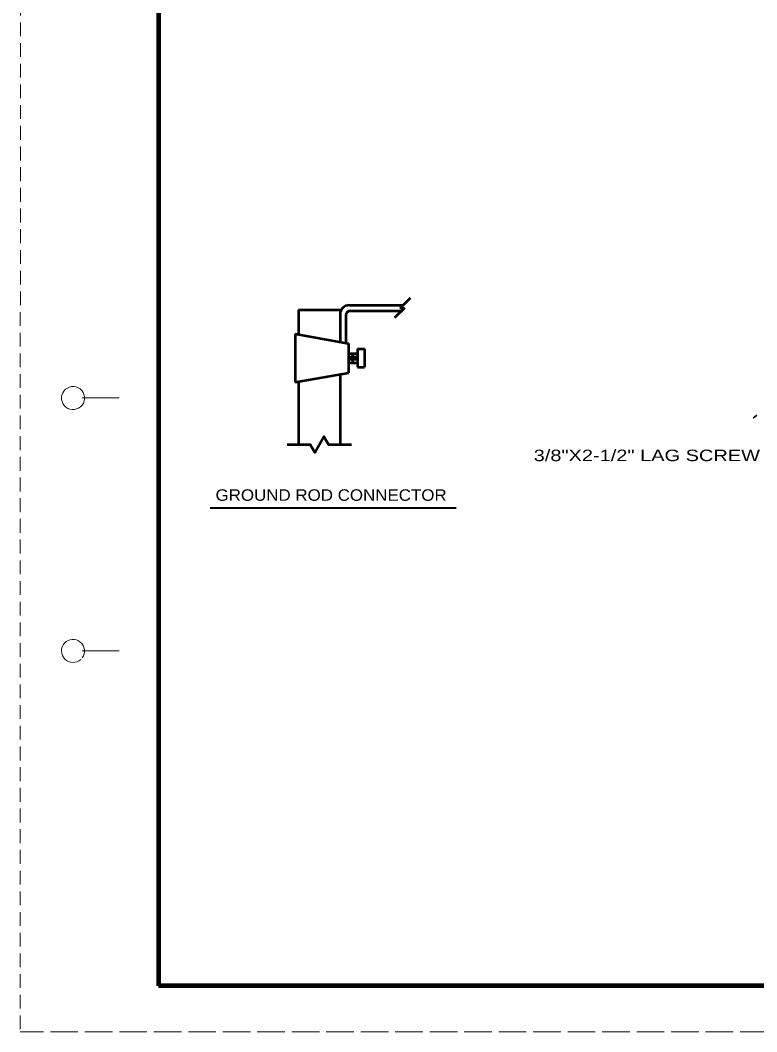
# Model space of a CAD drawing. Extents: x 12366 to 13046, y 9129 to 9570.
# Drawn here: x 12365.9 to 12526.1, y 9129.5 to 9349.5 of the extents above; entities that cross this region are included whole.
import ezdxf

# ---------------------------------------------------------------- set-up
doc = ezdxf.new("R2010")
doc.units = 0
doc.linetypes.add('LONG_DASHED', pattern=[7.5, 6, -1.5])
doc.linetypes.add('MEDIUM_DASHED', pattern=[4.5, 3, -1.5])
doc.layers.add('1', color=7, linetype='Continuous', lineweight=53)
doc.layers.add('61', color=7, linetype='Continuous', lineweight=35)

msp = doc.modelspace()

# ---------------------------------------------------------------- linework, layer by layer
at = {"layer": '1', "linetype": 'MEDIUM_DASHED', "lineweight": 13}
msp.add_line((12365.992, 9569.533), (12365.932, 9129.493), dxfattribs=at)
at = {"layer": '1'}
for p, q in [((12437.476, 9287.528), (12449.209, 9287.528)), ((12426.476, 9286.52), (12426.476, 9281.138)), ((12426.476, 9286.52), (12435.74, 9286.52)), ((12435.476, 9285.528), (12435.476, 9279.551)), ((12436.726, 9285.278), (12436.726, 9279.33)), ((12437.726, 9286.278), (12448.846, 9286.278)), ((12449.474, 9286.905), (12447.352, 9284.784)), ((12425.726, 9281.27), (12425.726, 9270.779)), ((12425.726, 9281.27), (12437.298, 9279.23)), ((12437.298, 9279.23), (12437.298, 9272.82)), ((12437.298, 9277.02), (12439.298, 9277.02)), ((12437.798, 9275.52), (12437.798, 9276.52)), ((12438.298, 9275.02), (12438.298, 9277.02)), ((12438.798, 9275.52), (12438.798, 9276.52)), ((12439.298, 9278.02), (12439.298, 9274.02)), ((12439.298, 9278.02), (12440.798, 9278.02)), ((12440.798, 9278.02), (12440.798, 9274.02)), ((12437.298, 9275.02), (12439.298, 9275.02)), ((12439.298, 9274.02), (12440.798, 9274.02)), ((12425.726, 9270.779), (12437.298, 9272.82)), ((12435.476, 9272.498), (12435.476, 9257.27)), ((12426.476, 9270.912), (12426.476, 9257.27))]:
    msp.add_line(p, q, dxfattribs=at)
at = {"layer": '1', "lineweight": 35}
msp.add_line((12525.317, 9262.922), (12526.085, 9263.578), dxfattribs=at)
at = {"layer": '1', "lineweight": 40}
msp.add_line((12407.255, 9243.427), (12460.728, 9243.427), dxfattribs=at)
at = {"layer": '1'}
for points in [[(12450.731, 9289.049), (12448.61, 9286.928), (12449.474, 9286.905)], [(12423.971, 9257.229), (12428.971, 9257.229), (12429.971, 9255.497), (12431.971, 9258.961), (12432.971, 9257.229), (12437.971, 9257.229)]]:
    msp.add_lwpolyline(points, dxfattribs=at)
for centre, radius, start in [((12437.476, 9285.528), 2, 90), ((12437.726, 9285.278), 1, 89.99931)]:
    msp.add_arc(centre, radius, start, 180, dxfattribs=at)
at = {"layer": '61', "lineweight": 13}
for p, q in [((12379.412, 9267.353), (12387.412, 9267.353)), ((12379.432, 9212.333), (12387.412, 9212.333))]:
    msp.add_line(p, q, dxfattribs=at)
at = {"layer": '61', "lineweight": 158}
msp.add_line((13035.052, 9139.493), (12395.992, 9139.513), dxfattribs=at)
at = {"layer": '61', "linetype": 'LONG_DASHED', "lineweight": 13}
msp.add_line((13045.992, 9129.513), (12365.932, 9129.493), dxfattribs=at)
at = {"layer": '61', "lineweight": 158}
msp.add_lwpolyline([(13035.032, 9559.533), (12395.992, 9559.533), (12395.992, 9139.513)], dxfattribs=at)
at = {"layer": '61', "lineweight": 13}
for centre, start, end in [((12377.409, 9267.334), 322.67175, 321.71615), ((12377.409, 9212.334), 323.13009, 312.31439)]:
    msp.add_arc(centre, 2.5, start, end, dxfattribs=at)

# ---------------------------------------------------------------- texts
at = {"layer": '1'}
for s, width, p in [('3/8"X2-1/2" LAG SCREW', 1.3, (12477.593, 9253.608)), ('GROUND ROD CONNECTOR', 1.1, (12408.41, 9244.983))]:
    msp.add_text(s, height=2.5, dxfattribs=dict(at, width=width)).set_placement(p)

doc.saveas('drawing.dxf')
